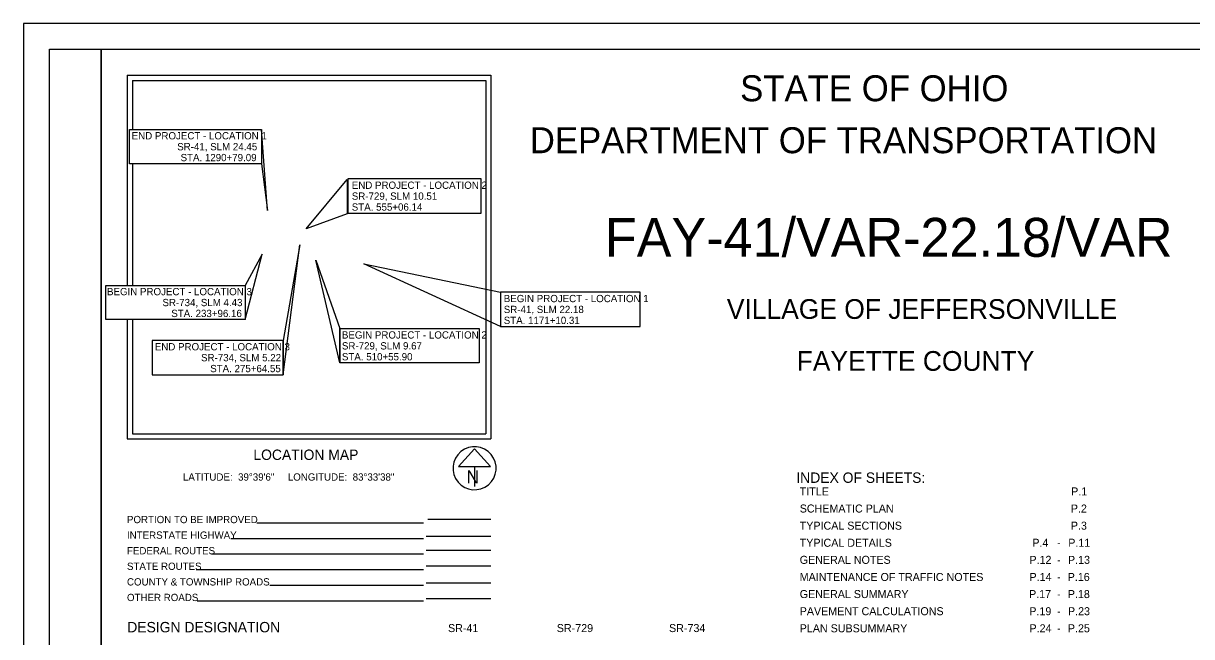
# Model space of a CAD drawing. Extents: x 0 to 34, y -1.6 to 22.
# Drawn here: x 0 to 22.48, y 10.19 to 22 of the extents above; entities that cross this region are included whole.
import ezdxf

# ---------------------------------------------------------------- set-up
doc = ezdxf.new("R2010")
doc.units = 0
for name, color, linetype in [('SH_Border', 7, 'Continuous'), ('SH_Cut_Line', 7, 'Continuous'), ('SH_Data', 7, 'Continuous'), ('SH_Text', 7, 'Continuous')]:
    doc.layers.add(name, color=color, linetype=linetype)

msp = doc.modelspace()

# ---------------------------------------------------------------- linework, layer by layer
at = {"layer": 'SH_Border'}
for points in [[(0.5, 21.5), (1.5, 21.5), (1.5, 0.5), (0.5, 0.5)], [(1.5, 21.5), (33.5, 21.5), (33.5, 0.5), (1.5, 0.5)]]:
    msp.add_lwpolyline(points, close=True, dxfattribs=at)
at = {"layer": 'SH_Cut_Line'}
msp.add_lwpolyline([(0, 0), (34, 0), (34, 22), (0, 22)], close=True, dxfattribs=at)
at = {"layer": 'SH_Data'}
for p, q in [((2, 21), (9, 21)), ((2, 21), (2, 16.956)), ((9, 21), (9, 14)), ((2.1, 20.9), (2.1, 19.957)), ((2.1, 20.9), (8.9, 20.9)), ((8.9, 20.9), (8.9, 14.1)), ((2.1, 19.298), (2.1, 16.956)), ((2, 16.297), (2, 14)), ((2.1, 16.297), (2.1, 14.1)), ((2, 14), (9, 14)), ((2.1, 14.1), (8.9, 14.1)), ((2.1, 14.1), (2.1, 14.1)), ((8.685, 13.809), (8.377, 13.468)), ((8.992, 13.468), (8.685, 13.809)), ((8.377, 13.468), (8.992, 13.468)), ((8.685, 13.468), (8.685, 13.081)), ((8.685, 13.435), (8.685, 13.435)), ((8.685, 13.435), (8.685, 13.435)), ((7.7, 12.377), (4.494, 12.377)), ((7.783, 12.455), (9, 12.455)), ((7.7, 12.077), (3.99, 12.077)), ((9, 12.121), (7.75, 12.121)), ((7.7, 11.777), (3.619, 11.777)), ((9, 11.849), (7.75, 11.849)), ((7.7, 11.477), (3.329, 11.477)), ((9, 11.549), (7.75, 11.549)), ((7.7, 11.177), (4.745, 11.177)), ((9, 11.222), (7.75, 11.222)), ((7.7, 10.877), (3.347, 10.877)), ((9, 10.922), (7.75, 10.922))]:
    msp.add_line(p, q, dxfattribs=at)
msp.add_arc((8.685, 13.435), 0.415, 129.7798, 129.7633, dxfattribs=at)
at = {"layer": 'SH_Text'}
for points in [[(2.042, 19.957), (4.585, 19.957), (4.585, 19.298), (2.042, 19.298)], [(4.7, 18.4), (4.585, 19.957), (4.585, 19.298)], [(5.445, 18.042), (6.231, 18.993), (6.231, 18.335)], [(8.814, 19.005), (6.242, 19.005), (6.242, 18.346), (8.814, 18.346)], [(4.599, 17.557), (4.271, 16.956), (4.271, 16.297)], [(5.321, 17.739), (5.003, 15.895), (5.003, 15.236)], [(5.631, 17.443), (6.09, 16.122), (6.09, 15.463)], [(6.55, 17.369), (9.186, 16.823), (9.186, 16.164)], [(1.585, 16.956), (4.271, 16.956), (4.271, 16.297), (1.585, 16.297)], [(11.872, 16.823), (9.186, 16.823), (9.186, 16.164), (11.872, 16.164)], [(6.09, 16.122), (8.775, 16.122), (8.775, 15.463), (6.09, 15.463)], [(5.003, 15.895), (2.476, 15.895), (2.476, 15.236), (5.003, 15.236)]]:
    msp.add_lwpolyline(points, close=True, dxfattribs=at)

# ---------------------------------------------------------------- texts
at = {"layer": 'SH_Data'}
for s, height, p in [('N', 0.25, (8.529, 13.144)), ('DESIGN DESIGNATION', 0.2, (2, 10.275))]:
    msp.add_text(s, height=height, dxfattribs=at).set_placement(p)
at = {"layer": 'SH_Text'}
for s, height, p in [('STATE OF OHIO', 0.5, (13.795, 20.5)), ('END PROJECT - LOCATION 1', 0.14, (2.085, 19.766)), ('DEPARTMENT OF TRANSPORTATION', 0.5, (9.747, 19.5)), ('SR-41, SLM 24.45', 0.14, (2.961, 19.556)), ('STA. 1290+79.09', 0.14, (3.026, 19.346)), ('END PROJECT - LOCATION 2', 0.14, (6.321, 18.814)), ('SR-729, SLM 10.51', 0.14, (6.321, 18.604)), ('STA. 555+06.14', 0.14, (6.321, 18.394)), ('FAY-41/VAR-22.18/VAR', 0.75, (11.192, 17.505)), ('BEGIN PROJECT - LOCATION 3', 0.14, (1.61, 16.765)), ('SR-734, SLM 4.43', 0.14, (2.677, 16.555)), ('BEGIN PROJECT - LOCATION 1', 0.14, (9.246, 16.632)), ('VILLAGE OF JEFFERSONVILLE', 0.38, (13.54, 16.31)), ('STA. 233+96.16', 0.14, (2.847, 16.345)), ('SR-41, SLM 22.18', 0.14, (9.246, 16.422)), ('STA. 1171+10.31', 0.14, (9.246, 16.212)), ('BEGIN PROJECT - LOCATION 2', 0.14, (6.131, 15.931)), ('END PROJECT - LOCATION 3', 0.14, (2.53, 15.704)), ('SR-729, SLM 9.67', 0.14, (6.131, 15.721)), ('SR-734, SLM 5.22', 0.14, (3.42, 15.494)), ('STA. 510+55.90', 0.14, (6.131, 15.511)), ('FAYETTE COUNTY', 0.38, (14.884, 15.31)), ('STA. 275+64.55', 0.14, (3.596, 15.284)), ('LOCATION MAP', 0.2, (4.427, 13.594)), ('LATITUDE:  39°39\'6"     LONGITUDE:  83°33\'38"', 0.14, (3.071, 13.196)), ('INDEX OF SHEETS:', 0.2, (14.877, 13.153)), ('TITLE', 0.154, (14.942, 12.911)), ('P.1', 0.154, (20.166, 12.911)), ('SCHEMATIC PLAN', 0.154, (14.942, 12.582)), ('P.2', 0.154, (20.16, 12.582)), ('PORTION TO BE IMPROVED', 0.14, (1.994, 12.377)), ('TYPICAL SECTIONS', 0.154, (14.942, 12.252)), ('P.3', 0.154, (20.16, 12.252)), ('INTERSTATE HIGHWAY', 0.14, (1.994, 12.077)), ('FEDERAL ROUTES', 0.14, (1.994, 11.777)), ('TYPICAL DETAILS', 0.154, (14.942, 11.923)), ('P.4', 0.154, (19.419, 11.923)), ('-', 0.154, (19.895, 11.923)), ('P.11', 0.154, (20.111, 11.923)), ('GENERAL NOTES', 0.154, (14.942, 11.594)), ('P.12', 0.154, (19.363, 11.594)), ('P.13', 0.154, (20.105, 11.594)), ('STATE ROUTES', 0.14, (1.994, 11.477)), ('-', 0.154, (19.895, 11.594)), ('COUNTY & TOWNSHIP ROADS', 0.14, (1.994, 11.177)), ('MAINTENANCE OF TRAFFIC NOTES', 0.154, (14.942, 11.264)), ('P.14', 0.154, (19.364, 11.264)), ('-', 0.154, (19.895, 11.264)), ('P.16', 0.154, (20.1, 11.264)), ('OTHER ROADS', 0.14, (1.994, 10.877)), ('GENERAL SUMMARY', 0.154, (14.942, 10.935)), ('P.17', 0.154, (19.356, 10.935)), ('P.18', 0.154, (20.102, 10.935)), ('-', 0.154, (19.895, 10.935)), ('PAVEMENT CALCULATIONS', 0.154, (14.942, 10.605)), ('P.19', 0.154, (19.361, 10.605)), ('-', 0.154, (19.895, 10.605)), ('P.23', 0.154, (20.105, 10.605)), ('SR-41', 0.154, (8.173, 10.28)), ('SR-729', 0.154, (10.267, 10.28)), ('SR-734', 0.154, (12.427, 10.28)), ('PLAN SUBSUMMARY', 0.154, (14.942, 10.276)), ('P.24', 0.154, (19.364, 10.276)), ('-', 0.154, (19.895, 10.276)), ('P.25', 0.154, (20.103, 10.276))]:
    msp.add_text(s, height=height, dxfattribs=at).set_placement(p)

doc.saveas('drawing.dxf')
